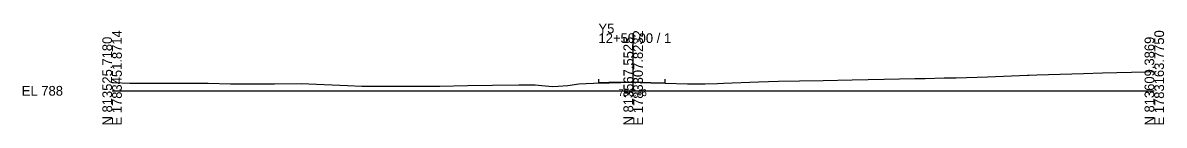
# Model space of a CAD drawing. Extents: x -26 to 1603, y -10 to 6526.
# Drawn here: x -25.7 to 302.8, y 2990.3 to 3019.4 of the extents above; entities that cross this region are included whole.
import ezdxf

# ---------------------------------------------------------------- set-up
doc = ezdxf.new("R2010")
doc.units = 0
for name, color, linetype in [('Exist Cross Section Cell', 7, 'Continuous'), ('Exist XS Center Line Elevation Label', 7, 'Continuous'), ('Exist XS Ground Line', 7, 'Continuous'), ('Prop XS EOT Tick Mark', 7, 'Continuous'), ('Prop XS Finish Grade Pavement', 7, 'Continuous')]:
    doc.layers.add(name, color=color, linetype=linetype)

msp = doc.modelspace()

# ---------------------------------------------------------------- linework, layer by layer
at = {"layer": 'Exist Cross Section Cell'}
for p, q in [((150, 3000), (150, 3016.59)), ((0, 3000), (150, 3000)), ((150, 3000), (300, 3000))]:
    msp.add_line(p, q, dxfattribs=at)
at = {"layer": 'Exist XS Ground Line'}
for p, q in [((191.83, 3002.79), (197.85, 3002.83)), ((197.85, 3002.83), (204.7, 3002.94)), ((204.7, 3002.94), (213.01, 3003.16)), ((213.01, 3003.16), (222.21, 3003.33)), ((222.21, 3003.33), (231.08, 3003.51)), ((231.08, 3003.51), (234.05, 3003.58)), ((234.05, 3003.58), (239.52, 3003.77)), ((239.52, 3003.77), (242.93, 3003.78)), ((242.93, 3003.78), (251.96, 3004.04)), ((251.96, 3004.04), (263.54, 3004.54)), ((263.54, 3004.54), (263.98, 3004.56)), ((263.98, 3004.56), (266.15, 3004.65)), ((266.15, 3004.65), (279.58, 3005.03)), ((279.58, 3005.03), (285.09, 3005.22)), ((285.09, 3005.22), (297.56, 3005.49)), ((297.56, 3005.49), (300, 3005.53)), ((0, 3002.35), (0.43, 3002.35)), ((0.43, 3002.35), (5.09, 3002.22)), ((5.09, 3002.22), (17.19, 3002.21)), ((17.19, 3002.21), (27.69, 3002.18)), ((27.69, 3002.18), (34.09, 3001.98)), ((34.09, 3001.98), (38.61, 3002)), ((38.61, 3002), (46.74, 3002.04)), ((46.74, 3002.04), (54.47, 3002.08)), ((54.47, 3002.08), (67.75, 3001.54)), ((67.75, 3001.54), (71.91, 3001.31)), ((71.91, 3001.31), (77.87, 3001.36)), ((77.87, 3001.36), (86.6, 3001.35)), ((86.6, 3001.35), (94.35, 3001.32)), ((94.35, 3001.32), (102.26, 3001.49)), ((102.26, 3001.49), (109.54, 3001.63)), ((109.54, 3001.63), (117.06, 3001.77)), ((117.06, 3001.77), (119.32, 3001.76)), ((119.32, 3001.76), (121.81, 3001.68)), ((121.81, 3001.68), (126.67, 3001.28)), ((126.67, 3001.28), (128.37, 3001.32)), ((128.37, 3001.32), (131.18, 3001.55)), ((131.18, 3001.55), (134.37, 3002)), ((134.37, 3002), (138.62, 3002.21)), ((138.62, 3002.21), (140.13, 3002.28)), ((140.13, 3002.28), (143.04, 3002.32)), ((143.04, 3002.32), (149.9, 3002.46)), ((149.9, 3002.46), (155.12, 3002.31)), ((155.12, 3002.31), (159.25, 3002.19)), ((159.25, 3002.19), (165.59, 3002.03)), ((165.59, 3002.03), (166.69, 3001.99)), ((166.69, 3001.99), (168.12, 3001.97)), ((168.12, 3001.97), (168.72, 3001.97)), ((168.72, 3001.97), (170.7, 3001.99)), ((170.7, 3001.99), (174.27, 3002.09)), ((174.27, 3002.09), (176.04, 3002.23)), ((176.04, 3002.23), (186.07, 3002.62)), ((186.07, 3002.62), (191.83, 3002.79))]:
    msp.add_line(p, q, dxfattribs=at)
at = {"layer": 'Prop XS EOT Tick Mark'}
for p, q in [((140.14, 3002.4), (140.14, 3003.4)), ((159.25, 3002.31), (159.25, 3003.31))]:
    msp.add_line(p, q, dxfattribs=at)
at = {"layer": 'Prop XS Finish Grade Pavement'}
for p, q in [((140.14, 3002.4), (143.03, 3002.45)), ((143.03, 3002.45), (149.91, 3002.59)), ((149.91, 3002.59), (155.12, 3002.43)), ((155.12, 3002.43), (159.25, 3002.31)), ((159.25, 3002.31), (159.28, 3002.31))]:
    msp.add_line(p, q, dxfattribs=at)

# ---------------------------------------------------------------- texts
at = {"layer": 'Exist Cross Section Cell'}
for s, p in [('Y5', (140, 3016.59)), ('12+50.00 / 1', (140, 3013.79)), ('EL 788', (-26, 2998.6))]:
    msp.add_text(s, height=2.8, dxfattribs=at).set_placement(p)
for s, p in [('E 1783451.8714', (2.8, 2990)), ('E 1783307.8232', (152.8, 2990)), ('E 1783163.7750', (302.8, 2990)), ('N 813525.7180', (0, 2990)), ('N 813567.5525', (150, 2990)), ('N 813609.3869', (300, 2990))]:
    msp.add_text(s, height=2.8, rotation=90, dxfattribs=at).set_placement(p)
at = {"layer": 'Exist XS Center Line Elevation Label'}
msp.add_text('790.46', height=2, dxfattribs=at).set_placement((145.73, 2998.46))

doc.saveas('drawing.dxf')
